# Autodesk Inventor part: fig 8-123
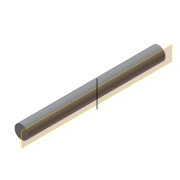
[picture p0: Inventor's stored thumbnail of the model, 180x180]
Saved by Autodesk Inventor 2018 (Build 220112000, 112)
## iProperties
Created: 2007-02
Part Number: fig 8-123
Document SubType Name: Modeling
Designer: Administrator
Density: 1 g/cm^3
Material: Generic
Appearance: Default
Author: Administrator
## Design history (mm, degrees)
node "Sketch1"
sketch "Sketch2"
  geometry: C1 r 5 at (0, 0); 1 further point
  constraints: 1 centre point, 1 coincident, 1 other
  dimensions: "d0" = 10 diameter of C1
extrude "Extrusion1" new body sketch "Sketch2" stored distance "d1" = 100; taper "d2" = 0 deg
workplane "Work Plane1"
sketch "Sketch3"
  geometry: L1 (0, 11)-(0, -8)
  constraints: 2 end point, 1 vertical
body "Solid1"
